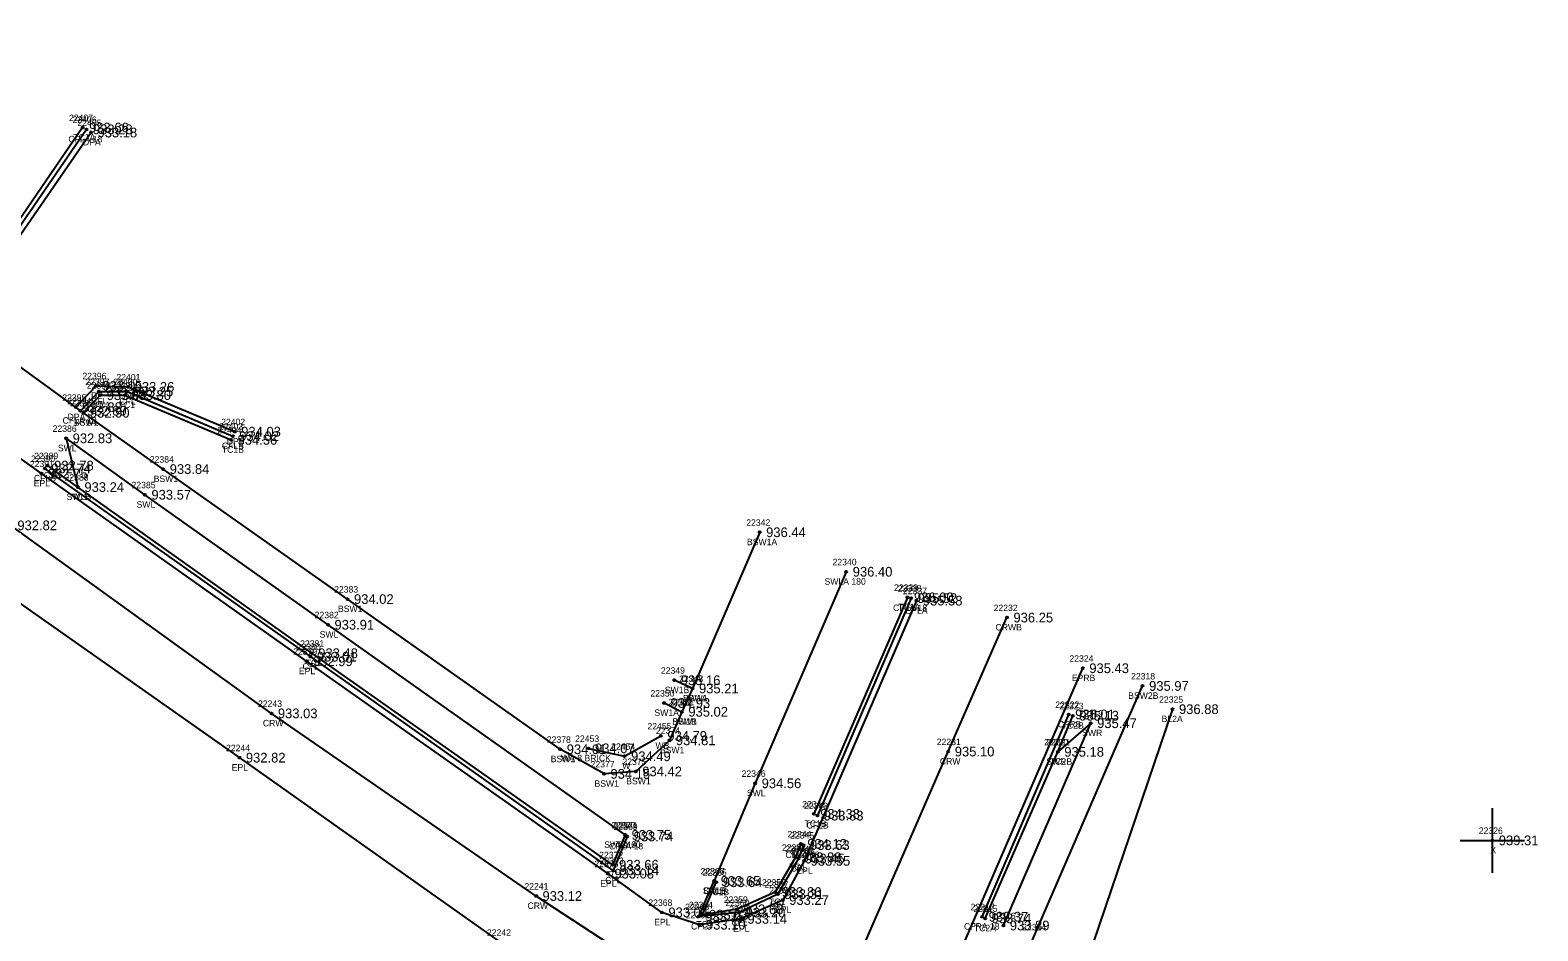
# Model space of a CAD drawing. Extents: x 1576181 to 1577685, y 1099396 to 1101490.
# Drawn here: x 1577213.8 to 1577447.2, y 1101343.5 to 1101482.9 of the extents above; entities that cross this region are included whole.
import ezdxf

# ---------------------------------------------------------------- set-up
doc = ezdxf.new("R2010")
doc.units = 0
for name, color, linetype in [('RD_DTM_BkLn1', 7, 'Continuous'), ('RD_DTM_BkLn2', 7, 'Continuous'), ('RD_DTM_BkLn_txCode', 7, 'Continuous'), ('RD_EX_BldgApp', 7, 'Continuous'), ('RD_EX_Conc', 7, 'Continuous'), ('RD_EX_Conc_txCode', 7, 'Continuous'), ('RD_EX_Driveway', 7, 'Continuous'), ('RD_EX_Driveway_txCode', 7, 'Continuous'), ('RD_EX_Misc', 7, 'Continuous'), ('RD_EX_Misc_txCode', 7, 'Continuous'), ('RD_EX_Road', 7, 'Continuous'), ('RD_EX_Road_txCode', 7, 'Continuous'), ('RD_EX_TX_Conc_ELEV', 7, 'Continuous'), ('RD_EX_TX_Driveway_ELEV', 7, 'Continuous'), ('RD_EX_TX_Misc_ELEV', 7, 'Continuous'), ('RD_EX_TX_Road_ELEV', 7, 'Continuous'), ('RD_HC_Survey_ELEV', 7, 'Continuous'), ('RD_HC_Survey_txCode', 7, 'Continuous'), ('RD_SMD_Locator', 7, 'Continuous')]:
    doc.layers.add(name, color=color, linetype=linetype)

msp = doc.modelspace()

# ---------------------------------------------------------------- linework, layer by layer
at = {"layer": 'RD_DTM_BkLn1'}
for points in [[(1577315, 1101333.96), (1577292.13, 1101348.94), (1577251.18, 1101377.2), (1577210.87, 1101406.3), (1577169.7, 1101434.76), (1577128.91, 1101464.09)], [(1576908.25, 1100441.74), (1576920.44, 1100463.64), (1576944.47, 1100507.42), (1576973.89, 1100560.12), (1576993.13, 1100594.33), (1577014.77, 1100632.79), (1577042.14, 1100681.68), (1577066.82, 1100725.12), (1577089.75, 1100766.04), (1577111.87, 1100810.02), (1577132.74, 1100857.48), (1577152.58, 1100903.02), (1577172.32, 1100949.02), (1577191.93, 1100994.6), (1577211.77, 1101040.76), (1577222.24, 1101065.99), (1577231.17, 1101086.4), (1577251.41, 1101132.37), (1577271.56, 1101178.18), (1577291.61, 1101224.24), (1577311.77, 1101270.05), (1577333.79, 1101320.46), (1577355.93, 1101371.29), (1577365.01, 1101392.03)], [(1577390.63, 1101377.85), (1577373.56, 1101327.56), (1577413.39, 1101299.59)]]:
    msp.add_lwpolyline(points, dxfattribs=at)
at = {"layer": 'RD_DTM_BkLn2'}
msp.add_line((1577349.61, 1101395.16), (1577335.11, 1101361.64), dxfattribs=at)
for points in [[(1577221.97, 1101467.87), (1577206.31, 1101445.07), (1577203.25, 1101442.28)], [(1577222.09, 1101423.72), (1577224.69, 1101426.44), (1577228.51, 1101426.46), (1577244.94, 1101419.53)], [(1577305.91, 1101358.4), (1577303.98, 1101353.78), (1577257.43, 1101386.51), (1577221.24, 1101412.22), (1577216.55, 1101415.55)], [(1577361.63, 1101345.48), (1577372.88, 1101371.25), (1577375.2, 1101376.84)], [(1577333.11, 1101357.01), (1577332.26, 1101354.94), (1577329.16, 1101349.55), (1577323.26, 1101346.88), (1577317.9, 1101346.05), (1577320.03, 1101351.07)]]:
    msp.add_lwpolyline(points, dxfattribs=at)
at = {"layer": 'RD_EX_BldgApp'}
msp.add_lwpolyline([(1577300.26, 1101371.79), (1577305.84, 1101370.57), (1577311.45, 1101373.71)], dxfattribs=at)
at = {"layer": 'RD_EX_Conc'}
for p, q in [((1577350.17, 1101395.04), (1577335.67, 1101361.38)), ((1577316.35, 1101381.05), (1577313.53, 1101382.33)), ((1577311.94, 1101378.81), (1577314.7, 1101377.45)), ((1577361.17, 1101345.74), (1577374.56, 1101377.04))]:
    msp.add_line(p, q, dxfattribs=at)
for points in [[(1577326.74, 1101405.23), (1577316.35, 1101381.05), (1577314.7, 1101377.45), (1577312.77, 1101373.03), (1577307.57, 1101368.22), (1577302.65, 1101367.84), (1577295.88, 1101371.65), (1577262.96, 1101394.89), (1577234.44, 1101415.01), (1577222.09, 1101423.72), (1577202.94, 1101437.61), (1577200.92, 1101438.92), (1577194.11, 1101443.95), (1577177.58, 1101455.53), (1577173.58, 1101458.39), (1577156.82, 1101470.2), (1577152.82, 1101472.9), (1577143.37, 1101479.79), (1577139.03, 1101482.93)], [(1577222.56, 1101467.58), (1577206.78, 1101444.68), (1577203.8, 1101441.89)], [(1577221.65, 1101424.04), (1577224.47, 1101427.01), (1577228.85, 1101427), (1577245.2, 1101420.1)], [(1577305.91, 1101358.4), (1577259.94, 1101390.92), (1577231.61, 1101411.04), (1577219.42, 1101419.77), (1577221.24, 1101412.22)], [(1577306.23, 1101358.15), (1577304.05, 1101352.9), (1577257.21, 1101385.98), (1577216.1, 1101415.11)], [(1577340.14, 1101399.12), (1577326.04, 1101366.38), (1577319.71, 1101351.27)], [(1577253.83, 1101078.11), (1577273.62, 1101123.24), (1577293.57, 1101168.95), (1577318.05, 1101225.09), (1577332.85, 1101259.38), (1577344.37, 1101285.79), (1577352.95, 1101305.61), (1577369.16, 1101342.63), (1577386, 1101381.45)], [(1577364.45, 1101344.37), (1577377.96, 1101375.68), (1577372.88, 1101371.25)], [(1577333.53, 1101356.82), (1577332.76, 1101354.73), (1577329.55, 1101349.22), (1577323.57, 1101346.37), (1577317.32, 1101345.76), (1577319.71, 1101351.27)]]:
    msp.add_lwpolyline(points, dxfattribs=at)
at = {"layer": 'RD_EX_Driveway'}
for points in [[(1577223.27, 1101467.09), (1577203.54, 1101438.52), (1577202.94, 1101437.61)], [(1577220.9, 1101424.58), (1577224.04, 1101427.91), (1577229.02, 1101427.73), (1577245.51, 1101420.8)]]:
    msp.add_lwpolyline(points, dxfattribs=at)
at = {"layer": 'RD_EX_Misc'}
for p, q in [((1577440.12, 1101352.55), (1577440.12, 1101362.55)), ((1577435.12, 1101357.55), (1577445.12, 1101357.55))]:
    msp.add_line(p, q, dxfattribs=at)
at = {"layer": 'RD_EX_Road'}
for points in [[(1577350.99, 1101394.65), (1577333.62, 1101354.38), (1577330.31, 1101348.32), (1577323.84, 1101345.4), (1577317.43, 1101344.5), (1577311.61, 1101346.41), (1577303.25, 1101352.4), (1577256.62, 1101385.27), (1577215.6, 1101414.32), (1577175.52, 1101442.94), (1577135.2, 1101471.71)], [(1577206.43, 1101064.72), (1577225.66, 1101106.5), (1577239.19, 1101137.5), (1577259.23, 1101183.34), (1577279.15, 1101229.33), (1577299.03, 1101275.07), (1577314.41, 1101310.73), (1577314.92, 1101317.44), (1577309.62, 1101326.25), (1577295.81, 1101333.97), (1577286.61, 1101341.78), (1577246.23, 1101370.35), (1577205.32, 1101399.1), (1577164.91, 1101427.55), (1577123.31, 1101456.71)], [(1577251.26, 1101061.34), (1577247.19, 1101065.51), (1577244.66, 1101070.88), (1577244.21, 1101077), (1577245.22, 1101081.73), (1577264.75, 1101126.91), (1577284.79, 1101172.93), (1577304.8, 1101218.29), (1577324.38, 1101263.32), (1577346.57, 1101314.36), (1577376.75, 1101384.19)]]:
    msp.add_lwpolyline(points, dxfattribs=at)
at = {"layer": 'RD_SMD_Locator'}
for centre in [(1577221.97, 1101467.87), (1577222.56, 1101467.58), (1577223.27, 1101467.09), (1577224.04, 1101427.91), (1577224.47, 1101427.01), (1577224.69, 1101426.44), (1577228.51, 1101426.46), (1577228.85, 1101427), (1577229.02, 1101427.73), (1577220.9, 1101424.58), (1577221.65, 1101424.04), (1577222.09, 1101423.72), (1577222.09, 1101423.72), (1577219.42, 1101419.77), (1577244.94, 1101419.53), (1577245.2, 1101420.1), (1577245.51, 1101420.8), (1577216.1, 1101415.11), (1577216.55, 1101415.55), (1577234.44, 1101415.01), (1577215.6, 1101414.32), (1577221.24, 1101412.22), (1577221.24, 1101412.22), (1577231.61, 1101411.04), (1577326.74, 1101405.23), (1577340.14, 1101399.12), (1577262.96, 1101394.89), (1577349.61, 1101395.16), (1577350.17, 1101395.04), (1577350.99, 1101394.65), (1577365.01, 1101392.03), (1577259.94, 1101390.92), (1577257.43, 1101386.51), (1577256.62, 1101385.27), (1577257.21, 1101385.98), (1577376.75, 1101384.19), (1577313.53, 1101382.33), (1577316.35, 1101381.05), (1577316.35, 1101381.05), (1577386, 1101381.45), (1577251.18, 1101377.2), (1577311.94, 1101378.81), (1577314.7, 1101377.45), (1577314.7, 1101377.45), (1577390.63, 1101377.85), (1577374.56, 1101377.04), (1577375.2, 1101376.84), (1577377.96, 1101375.68), (1577311.45, 1101373.71), (1577312.77, 1101373.03), (1577246.23, 1101370.35), (1577295.88, 1101371.65), (1577300.26, 1101371.79), (1577305.84, 1101370.57), (1577355.93, 1101371.29), (1577372.88, 1101371.25), (1577372.88, 1101371.25), (1577302.65, 1101367.84), (1577307.57, 1101368.22), (1577326.04, 1101366.38), (1577335.11, 1101361.64), (1577335.67, 1101361.38), (1577305.91, 1101358.4), (1577305.91, 1101358.4), (1577306.23, 1101358.15), (1577333.11, 1101357.01), (1577333.53, 1101356.82), (1577440.12, 1101357.55), (1577332.26, 1101354.94), (1577332.76, 1101354.73), (1577333.62, 1101354.38), (1577303.25, 1101352.4), (1577303.98, 1101353.78), (1577304.05, 1101352.9), (1577319.71, 1101351.27), (1577319.71, 1101351.27), (1577320.03, 1101351.07), (1577329.16, 1101349.55), (1577329.55, 1101349.22), (1577292.13, 1101348.94), (1577323.26, 1101346.88), (1577330.31, 1101348.32), (1577311.61, 1101346.41), (1577317.32, 1101345.76), (1577317.43, 1101344.5), (1577317.9, 1101346.05), (1577323.57, 1101346.37), (1577323.84, 1101345.4), (1577361.17, 1101345.74), (1577361.63, 1101345.48), (1577364.45, 1101344.37)]:
    msp.add_circle(centre, 0.15, dxfattribs=at)

# ---------------------------------------------------------------- texts
at = {"layer": 'RD_DTM_BkLn_txCode'}
for s, p in [('22325', (1577388.55, 1101378.85)), ('BL2A', (1577388.94, 1101375.85))]:
    msp.add_text(s, height=1, dxfattribs=at).set_placement(p)
at = {"layer": 'RD_EX_Conc_txCode'}
for s, p in [('22407', (1577219.85, 1101468.87)), ('22406', (1577220.41, 1101468.58)), ('CFLA 18', (1577219.76, 1101465.58)), ('TC1A', (1577220.52, 1101465.87)), ('22397', (1577222.39, 1101428.01)), ('22400', (1577226.7, 1101428)), ('22398', (1577222.61, 1101427.44)), ('22399', (1577226.43, 1101427.46)), ('22394', (1577219.58, 1101425.04)), ('22392', (1577220.01, 1101424.72)), ('22393', (1577220.01, 1101424.72)), ('CFL', (1577223.27, 1101425.01)), ('TC1', (1577223.73, 1101424.44)), ('TC1', (1577227.55, 1101424.46)), ('CFL', (1577227.65, 1101425)), ('22386', (1577217.32, 1101420.77)), ('CFLA 18', (1577218.86, 1101422.04)), ('TC1A', (1577220.64, 1101421.72)), ('BSW1', (1577220.61, 1101421.72)), ('22403', (1577243.08, 1101421.1)), ('22404', (1577242.83, 1101420.53)), ('22390', (1577213.98, 1101416.11)), ('22389', (1577214.47, 1101416.55)), ('SWL', (1577218.13, 1101417.77)), ('22384', (1577232.36, 1101416.01)), ('TC1B', (1577243.51, 1101417.53)), ('CFLB', (1577243.52, 1101418.1)), ('CFLB', (1577214.43, 1101413.11)), ('TC1B', (1577215.12, 1101413.55)), ('22387', (1577219.16, 1101413.22)), ('22388', (1577219.16, 1101413.22)), ('22385', (1577229.53, 1101412.04)), ('BSW1', (1577232.96, 1101413.01)), ('SWLB', (1577219.48, 1101410.22)), ('TC1', (1577220.28, 1101410.22)), ('SWL', (1577230.31, 1101409.04)), ('22342', (1577324.66, 1101406.23)), ('BSW1A', (1577324.77, 1101403.23)), ('22340', (1577338.02, 1101400.12)), ('22383', (1577260.88, 1101395.89)), ('SWLA 180', (1577336.77, 1101397.12)), ('22339', (1577347.53, 1101396.16)), ('22338', (1577348.09, 1101396.04)), ('BSW1', (1577261.48, 1101392.89)), ('CFLA 18', (1577347.38, 1101393.04)), ('TC1A', (1577348.16, 1101393.16)), ('22382', (1577257.87, 1101391.92)), ('SWL', (1577258.65, 1101388.92)), ('22380', (1577255.09, 1101386.98)), ('22381', (1577255.63, 1101387.51)), ('CFL', (1577256, 1101383.98)), ('TC1', (1577256.47, 1101384.51)), ('22349', (1577311.45, 1101383.33)), ('22347', (1577314.27, 1101382.05)), ('22348', (1577314.27, 1101382.05)), ('22318', (1577384.21, 1101382.45)), ('22350', (1577309.83, 1101379.81)), ('SW1B', (1577312.05, 1101380.33)), ('SW1A', (1577314.85, 1101379.05)), ('BSW1', (1577314.87, 1101379.05)), ('BSW2B', (1577383.77, 1101379.45)), ('SW1A', (1577310.45, 1101376.81)), ('22352', (1577312.62, 1101378.45)), ('22351', (1577312.91, 1101378.45)), ('22322', (1577372.48, 1101378.04)), ('22323', (1577373.12, 1101377.84)), ('22319', (1577376.16, 1101376.68)), ('22374', (1577310.69, 1101374.03)), ('SW1B', (1577313.22, 1101375.45)), ('BSW1', (1577313.22, 1101375.45)), ('CFRB', (1577372.86, 1101375.04)), ('TC2B', (1577373.48, 1101374.84)), ('22378', (1577293.8, 1101372.65)), ('22320', (1577370.76, 1101372.25)), ('22321', (1577371.08, 1101372.25)), ('SWR', (1577376.64, 1101373.68)), ('BSW1', (1577294.4, 1101369.65)), ('BSW1', (1577311.29, 1101371.03)), ('22377', (1577300.57, 1101368.84)), ('22375', (1577305.5, 1101369.22)), ('22346', (1577323.94, 1101367.38)), ('SWRB', (1577371.09, 1101369.25)), ('TC2', (1577371.63, 1101369.25)), ('BSW1', (1577301.17, 1101365.84)), ('BSW1', (1577306.09, 1101366.22)), ('SWL', (1577324.75, 1101364.38)), ('22341', (1577333.32, 1101362.64)), ('22343', (1577333.59, 1101362.38)), ('22370', (1577303.79, 1101359.4)), ('22371', (1577304.12, 1101359.4)), ('22369', (1577304.13, 1101359.15)), ('22344', (1577331.03, 1101358.01)), ('22345', (1577331.45, 1101357.82)), ('TC1B', (1577333.68, 1101359.64)), ('CFLB', (1577334, 1101359.38)), ('SWLA 60', (1577302.68, 1101356.4)), ('CFLA 18', (1577303.43, 1101356.15)), ('TC1A', (1577304.46, 1101356.4)), ('22353', (1577330.18, 1101355.94)), ('22354', (1577330.68, 1101355.73)), ('22372', (1577301.9, 1101354.78)), ('22373', (1577301.97, 1101353.9)), ('CFLA 18', (1577330.73, 1101354.82)), ('TC1A', (1577331.66, 1101355.01)), ('CFL', (1577302.84, 1101350.9)), ('TC1', (1577303.02, 1101351.78)), ('22366', (1577317.58, 1101352.27)), ('22367', (1577317.61, 1101352.27)), ('22365', (1577317.92, 1101352.07)), ('TC1', (1577331.3, 1101352.94)), ('CFL', (1577331.55, 1101352.73)), ('SWLB', (1577317.94, 1101349.27)), ('CFLB', (1577318.03, 1101349.27)), ('TC1B', (1577318.59, 1101349.07)), ('22358', (1577327.08, 1101350.55)), ('22357', (1577327.47, 1101350.22)), ('22363', (1577315.22, 1101346.76)), ('22364', (1577315.79, 1101347.05)), ('22359', (1577321.18, 1101347.88)), ('22360', (1577321.43, 1101347.37)), ('TC1', (1577328.2, 1101347.55)), ('CFL', (1577328.34, 1101347.22)), ('22317', (1577359.38, 1101346.74)), ('22315', (1577359.83, 1101346.48)), ('CFL', (1577316.12, 1101343.76)), ('TC1', (1577316.93, 1101344.05)), ('TC1', (1577322.3, 1101344.88)), ('CFL', (1577322.37, 1101344.37)), ('CFRA 18', (1577358.36, 1101343.74)), ('22316', (1577362.63, 1101345.37)), ('22314', (1577367.36, 1101343.63)), ('TC2A', (1577359.89, 1101343.48))]:
    msp.add_text(s, height=1, dxfattribs=at).set_placement(p)
at = {"layer": 'RD_EX_Driveway_txCode'}
for s, p in [('22405', (1577221.16, 1101468.09)), ('DPA', (1577222.01, 1101465.09)), ('22396', (1577221.93, 1101428.91)), ('22401', (1577227.19, 1101428.73)), ('22395', (1577218.82, 1101425.58)), ('DP', (1577223.26, 1101425.91)), ('DP', (1577228.25, 1101425.73)), ('DPA', (1577219.63, 1101422.58)), ('22402', (1577243.4, 1101421.8)), ('DPB', (1577244.26, 1101418.8))]:
    msp.add_text(s, height=1, dxfattribs=at).set_placement(p)
at = {"layer": 'RD_EX_Misc_txCode'}
for s, p in [('22455', (1577309.37, 1101374.71)), ('22453', (1577298.18, 1101372.79)), ('WB', (1577310.61, 1101371.71)), ('WA 8 BRICK', (1577295.99, 1101369.79)), ('22454', (1577303.76, 1101371.57)), ('W', (1577305.47, 1101368.57)), ('22326', (1577438.02, 1101358.55)), ('X', (1577439.81, 1101355.55))]:
    msp.add_text(s, height=1, dxfattribs=at).set_placement(p)
at = {"layer": 'RD_EX_Road_txCode'}
for s, p in [('22391', (1577213.8, 1101415.32)), ('EPL', (1577214.39, 1101412.32)), ('22337', (1577348.92, 1101395.65)), ('EPLA', (1577349.3, 1101392.65)), ('22379', (1577254.54, 1101386.27)), ('22324', (1577374.67, 1101385.19)), ('EPL', (1577255.42, 1101383.27)), ('EPRB', (1577375.04, 1101382.19)), ('22244', (1577244.15, 1101371.35)), ('EPL', (1577245.03, 1101368.35)), ('22355', (1577331.54, 1101355.38)), ('22376', (1577301.15, 1101353.4)), ('EPL', (1577332.41, 1101352.38)), ('EPL', (1577302.05, 1101350.4)), ('22356', (1577328.21, 1101349.32)), ('22368', (1577309.51, 1101347.41)), ('22361', (1577322.02, 1101346.4)), ('EPL', (1577329.1, 1101346.32)), ('EPL', (1577310.41, 1101344.41)), ('22362', (1577315.33, 1101345.5)), ('22242', (1577284.53, 1101342.78)), ('EPL', (1577322.63, 1101343.4))]:
    msp.add_text(s, height=1, dxfattribs=at).set_placement(p)
at = {"layer": 'RD_EX_TX_Conc_ELEV'}
for s, p in [('933.66', (1577222.97, 1101467.12)), ('933.23', (1577223.56, 1101466.83)), ('933.15', (1577225.47, 1101426.26)), ('933.68', (1577225.69, 1101425.69)), ('933.80', (1577229.51, 1101425.71)), ('933.25', (1577229.85, 1101426.25)), ('932.89', (1577222.65, 1101423.29)), ('932.90', (1577223.09, 1101422.97)), ('932.90', (1577223.09, 1101422.97)), ('932.83', (1577220.42, 1101419.02)), ('934.56', (1577245.94, 1101418.78)), ('934.02', (1577246.2, 1101419.35)), ('932.74', (1577217.1, 1101414.36)), ('932.78', (1577217.55, 1101414.8)), ('933.84', (1577235.44, 1101414.26)), ('933.24', (1577222.24, 1101411.47)), ('933.24', (1577222.24, 1101411.47)), ('933.57', (1577232.61, 1101410.29)), ('936.44', (1577327.74, 1101404.48)), ('936.40', (1577341.14, 1101398.37)), ('934.02', (1577263.96, 1101394.14)), ('936.00', (1577350.61, 1101394.41)), ('935.52', (1577351.17, 1101394.29)), ('933.91', (1577260.94, 1101390.17)), ('933.01', (1577258.21, 1101385.23)), ('933.48', (1577258.43, 1101385.76)), ('935.16', (1577314.53, 1101381.58)), ('935.97', (1577387, 1101380.7)), ('935.21', (1577317.35, 1101380.3)), ('935.21', (1577317.35, 1101380.3)), ('934.93', (1577312.94, 1101378.06)), ('935.02', (1577315.7, 1101376.7)), ('935.02', (1577315.7, 1101376.7)), ('935.01', (1577375.56, 1101376.29)), ('935.13', (1577376.2, 1101376.09)), ('935.47', (1577378.96, 1101374.93)), ('934.81', (1577313.77, 1101372.28)), ('934.01', (1577296.88, 1101370.9)), ('935.18', (1577373.88, 1101370.5)), ('935.18', (1577373.88, 1101370.5)), ('934.15', (1577303.65, 1101367.09)), ('934.42', (1577308.57, 1101367.47)), ('934.56', (1577327.04, 1101365.63)), ('934.38', (1577336.11, 1101360.89)), ('933.83', (1577336.67, 1101360.63)), ('933.75', (1577306.91, 1101357.65)), ('933.75', (1577306.91, 1101357.65)), ('933.74', (1577307.23, 1101357.4)), ('934.12', (1577334.11, 1101356.26)), ('933.63', (1577334.53, 1101356.07)), ('933.66', (1577304.98, 1101353.03)), ('933.88', (1577333.26, 1101354.19)), ('933.45', (1577333.76, 1101353.98)), ('933.14', (1577305.05, 1101352.15)), ('933.65', (1577320.71, 1101350.52)), ('933.65', (1577320.71, 1101350.52)), ('933.64', (1577321.03, 1101350.32)), ('933.86', (1577330.16, 1101348.8)), ('933.31', (1577330.55, 1101348.47)), ('933.68', (1577324.26, 1101346.13)), ('933.20', (1577324.57, 1101345.62)), ('933.15', (1577318.32, 1101345.01)), ('933.63', (1577318.9, 1101345.3)), ('933.37', (1577362.17, 1101344.99)), ('933.74', (1577362.63, 1101344.73)), ('933.89', (1577365.45, 1101343.62))]:
    msp.add_text(s, height=1.5, dxfattribs=at).set_placement(p)
at = {"layer": 'RD_EX_TX_Driveway_ELEV'}
for s, p in [('933.18', (1577224.27, 1101466.34)), ('933.15', (1577225.04, 1101427.16)), ('933.26', (1577230.02, 1101426.98)), ('932.88', (1577221.9, 1101423.83)), ('934.03', (1577246.51, 1101420.05))]:
    msp.add_text(s, height=1.5, dxfattribs=at).set_placement(p)
at = {"layer": 'RD_EX_TX_Misc_ELEV'}
for s, p in [('936.88', (1577391.63, 1101377.1)), ('934.79', (1577312.45, 1101372.96)), ('934.07', (1577301.26, 1101371.04)), ('934.49', (1577306.84, 1101369.82)), ('939.31', (1577441.12, 1101356.8))]:
    msp.add_text(s, height=1.5, dxfattribs=at).set_placement(p)
at = {"layer": 'RD_EX_TX_Road_ELEV'}
for s, p in [('932.75', (1577216.6, 1101413.57)), ('935.58', (1577351.99, 1101393.9)), ('932.99', (1577257.62, 1101384.52)), ('935.43', (1577377.75, 1101383.44)), ('932.82', (1577247.23, 1101369.6)), ('933.55', (1577334.62, 1101353.63)), ('933.08', (1577304.25, 1101351.65)), ('933.04', (1577312.61, 1101345.66)), ('933.27', (1577331.31, 1101347.57)), ('933.10', (1577318.43, 1101343.75)), ('933.14', (1577324.84, 1101344.65))]:
    msp.add_text(s, height=1.5, dxfattribs=at).set_placement(p)
at = {"layer": 'RD_HC_Survey_ELEV'}
for s, p in [('932.82', (1577211.87, 1101405.55)), ('936.25', (1577366.01, 1101391.28)), ('933.03', (1577252.18, 1101376.45)), ('935.10', (1577356.93, 1101370.54)), ('933.12', (1577293.13, 1101348.19))]:
    msp.add_text(s, height=1.5, dxfattribs=at).set_placement(p)
at = {"layer": 'RD_HC_Survey_txCode'}
for s, p in [('22232', (1577362.94, 1101393.03)), ('CRWB', (1577363.23, 1101390.03)), ('22243', (1577249.1, 1101378.2)), ('CRW', (1577249.86, 1101375.2)), ('22231', (1577354.14, 1101372.29)), ('CRW', (1577354.62, 1101369.29)), ('22241', (1577290.33, 1101349.94)), ('CRW', (1577290.81, 1101346.94))]:
    msp.add_text(s, height=1, dxfattribs=at).set_placement(p)

doc.saveas('drawing.dxf')
